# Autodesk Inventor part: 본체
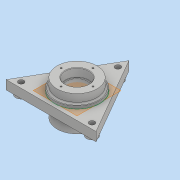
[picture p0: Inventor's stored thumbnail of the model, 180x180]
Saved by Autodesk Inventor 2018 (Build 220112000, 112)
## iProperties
Created: 2023-04
Part Number: 본체
Material: 일반
Document SubType Name: Modeling
Designer: home
Density: 1 g/cm^3
Appearance: 기본값
Author: home
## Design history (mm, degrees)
sketch "스케치1"
  geometry: C1 r 40 at (0, 0); 1 further point
  constraints: 1 centre point, 1 coincident
  dimensions: "d0" = 40 radius of C1
extrude "돌출1" new body sketch "스케치1" distance "d1" = 70; taper "d2" = 0 deg
node "작업 평면1"
sketch "스케치2"
  geometry: C1 r 45 at (0, 0); 1 further point
  constraints: 1 centre point, 1 coincident
  dimensions: "d4" = 90 diameter of C1
extrude "돌출2" join sketch "스케치2" distance "d5" = 5; taper "d6" = 0 deg
sketch "스케치3"
  geometry: C1 r 45 at (0, 0) reference; C2 r 40 at (0, 0) reference; 1 further point
  node "절단 모서리 투영1"
hole "구멍1" diameter "d18" = 42; stored, may be unused: countersink angle "d22" = 90 deg, drill point angle "d24" = 118 deg; dims "d16" = 10, "d17" = 10, "d19" = 6, "d20" = 47, "d21" = 17, "d23" = 36
hole "구멍2" diameter "d27" = 42; stored, may be unused: countersink angle "d31" = 90 deg, drill point angle "d33" = 118 deg; dims "d25" = 10, "d26" = 10, "d28" = 6, "d29" = 47, "d30" = 17, "d32" = 36
fillet "모깎기1" dims "d34" = 0.6
chamfer "모따기1" distance "d35" = 1; stored, may be unused: second distance "d36" = 2, angle "d37" = 45 deg
sketch "스케치4" dims "d38" = 64
  geometry: 3 further points
  constraints: 1 coincident, 1 vertical alignment, 2 other
hole "구멍3" sketch "스케치4" at (0, 32) diameter "d39" = 3.242; stored, may be unused: countersink angle "d43" = 90 deg, drill point angle "d45" = 118 deg; dims "d40" = 8, "d41" = 4, "d42" = 2, "d44" = 10
node "작업 평면2"
sketch "스케치5"
  geometry: L1 (0, 0)-(0, 82); C1 r 11 at (0, 82); C2 r 11 at (-71.014, -41); C3 r 11 at (71.014, -41)
  constraints: 3 centre point, 2 end point, 1 coincident, 1 vertical, 7 other
  dimensions: "d49" = 82 distance of L1.start L1.end; "d50" = 22 diameter of C1; "d53" = 360 deg dimension on L1.start C1.centre (derived)
extrude "돌출3" join sketch "스케치5" distance "d55" = 22; taper "d56" = 0 deg
sketch "스케치6"
  geometry: L1 (0, 104)-(-90.067, -52); L2 (-90.067, -52)-(90.067, -52); L3 (0, 104)-(90.067, -52); C1 r 21 at (0, 0) reference; C2 r 45 at (0, 0) reference; C3 r 40 at (0, 0) reference; C4 r 11 at (71.014, -41) reference; C5 r 11 at (0, 82) reference; C6 r 11 at (-71.014, -41) reference; C7 r 11 at (71.014, -41) reference; C8 r 11 at (0, 82); C9 r 11 at (0, 82) reference; 3 further points
  constraints: 7 tangent, 6 end point, 2 horizontal, 1 centre point, 1 coincident, 1 horizontal alignment, 1 other
  dimensions: "d61" = 22 diameter of C8
extrude "돌출4" join sketch "스케치6" distance "d62" = 18; taper "d63" = 0 deg
sketch "스케치7"
  geometry: C1 r 5.5 at (0, 0); C2 r 5.5 at (-71.014, -123); C3 r 5.5 at (71.014, -123); 1 further point
  constraints: 3 centre point, 7 other
  dimensions: "d64" = 11 diameter of C1; "d67" = 360 deg dimension on point (0, -82) C1.centre (derived)
extrude "돌출5" cut sketch "스케치7" distance "d69" = 25; taper "d70" = 0 deg
fillet "모깎기2" dims "d71" = 3
fillet "모깎기3" dims "d72" = 3
node "솔리드1"
pattern_circular "원형 패턴1" dims angle "d47" = 360 deg
mirror "미러1"
node "절단 모서리 투영2"
other parameters: "d3" = -23
